// Mitsubishi GX Works2 project: 55.编码器多点定位控制   PLC: FX3U/FX3UC

PROGRAM MAIN
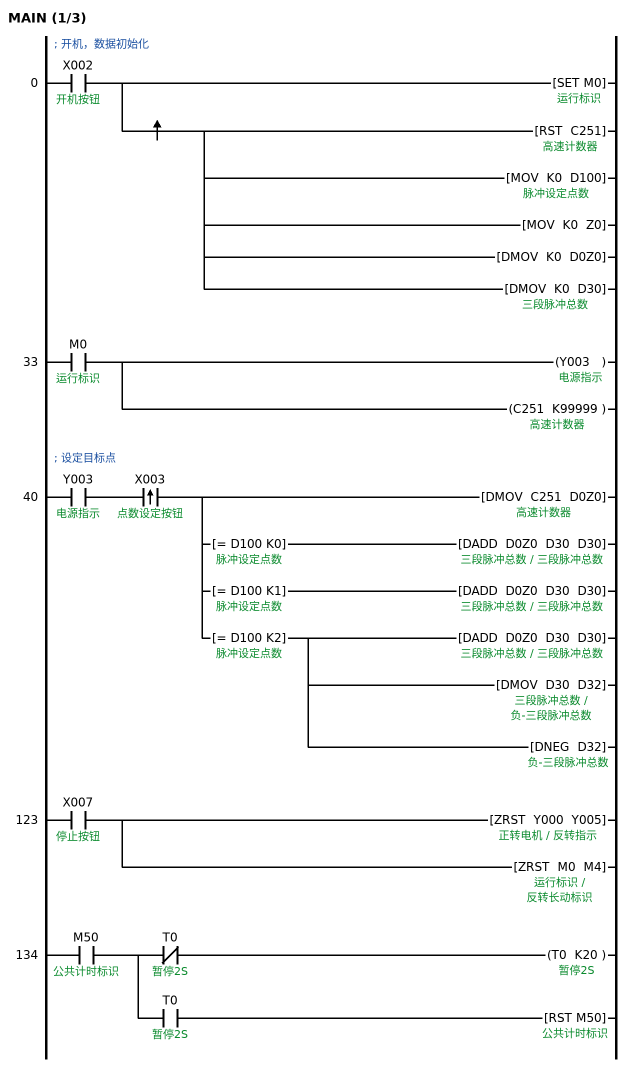
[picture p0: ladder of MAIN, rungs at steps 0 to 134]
; 开机，数据初始化
0     LD      X002  ; 开机按钮
      SET     M0  ; 运行标识
      MEP
      RST     C251  ; 高速计数器
      MOV     K0 D100  ; 脉冲设定点数
      MOV     K0 Z0
      DMOV    K0 D0Z0
      DMOV    K0 D30  ; 三段脉冲总数
33    LD      M0  ; 运行标识
      OUT     Y003  ; 电源指示
      OUT     C251 K99999  ; 高速计数器
; 设定目标点
40    LD      Y003  ; 电源指示
      ANDP    X003  ; 点数设定按钮
      DMOV    C251 D0Z0
      MPS
      AND=    D100 K0  ; 脉冲设定点数
      DADD    D0Z0 D30 D30
      MRD
      AND=    D100 K1  ; 脉冲设定点数
      DADD    D0Z0 D30 D30
      MPP
      AND=    D100 K2  ; 脉冲设定点数
      DADD    D0Z0 D30 D30
      DMOV    D30 D32  ; 负-三段脉冲总数
      DNEG    D32
        [note] 取反：得出反转电机的脉冲数
123   LD      X007  ; 停止按钮
      ZRST    Y000 Y005  ; 正转电机 / 反转指示
      ZRST    M0 M4  ; 反转长动标识
134   LD      M50  ; 公共计时标识
      MPS
      ANI     T0  ; 暂停2S
      OUT     T0 K20  ; 暂停2S
      MPP
      AND     T0  ; 暂停2S
      RST     M50  ; 公共计时标识
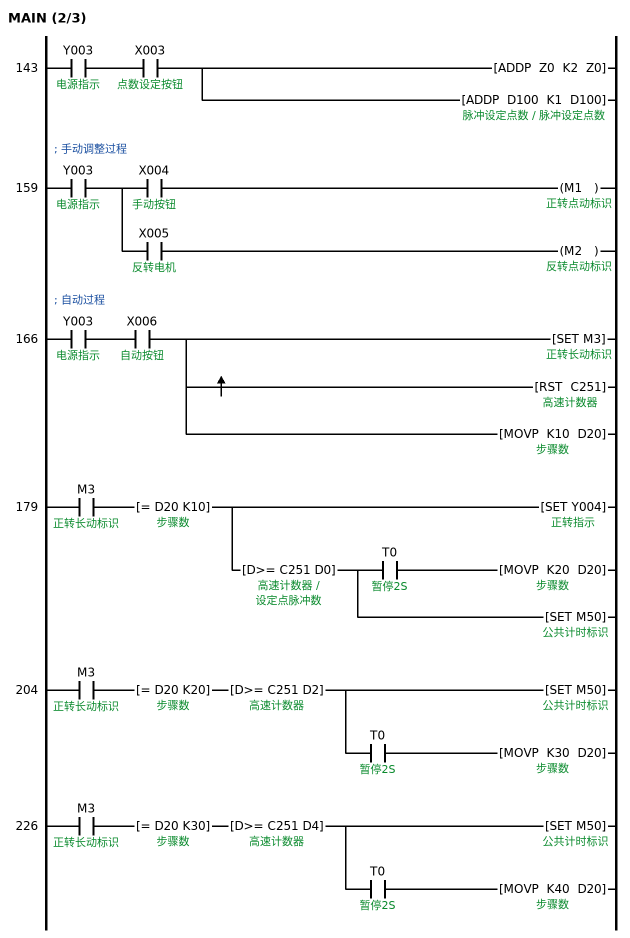
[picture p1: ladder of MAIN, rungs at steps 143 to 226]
143   LD      Y003  ; 电源指示
      AND     X003  ; 点数设定按钮
      ADDP    Z0 K2 Z0
        [note] 目标脉冲数z0自加二
      ADDP    D100 K1 D100
        [note] 目标点数D100自加一
; 手动调整过程
159   LD      Y003  ; 电源指示
      MPS
      AND     X004  ; 手动按钮
      OUT     M1  ; 正转点动标识
      MPP
      AND     X005  ; 反转电机
      OUT     M2  ; 反转点动标识
; 自动过程
166   LD      Y003  ; 电源指示
      AND     X006  ; 自动按钮
      SET     M3  ; 正转长动标识
      MPS
      MEP
      RST     C251  ; 高速计数器
      MPP
      MOVP    K10 D20  ; 步骤数
179   LD      M3  ; 正转长动标识
      AND=    D20 K10  ; 步骤数
      SET     Y004  ; 正转指示
      ANDD>=  C251 D0  ; 高速计数器 / 设定点脉冲数
      MPS
      AND     T0  ; 暂停2S
      MOVP    K20 D20
      MPP
      SET     M50  ; 公共计时标识
204   LD      M3  ; 正转长动标识
      AND=    D20 K20  ; 步骤数
      ANDD>=  C251 D2  ; 高速计数器
      SET     M50  ; 公共计时标识
      AND     T0  ; 暂停2S
      MOVP    K30 D20
226   LD      M3  ; 正转长动标识
      AND=    D20 K30  ; 步骤数
      ANDD>=  C251 D4  ; 高速计数器
      SET     M50  ; 公共计时标识
      AND     T0  ; 暂停2S
      MOVP    K40 D20
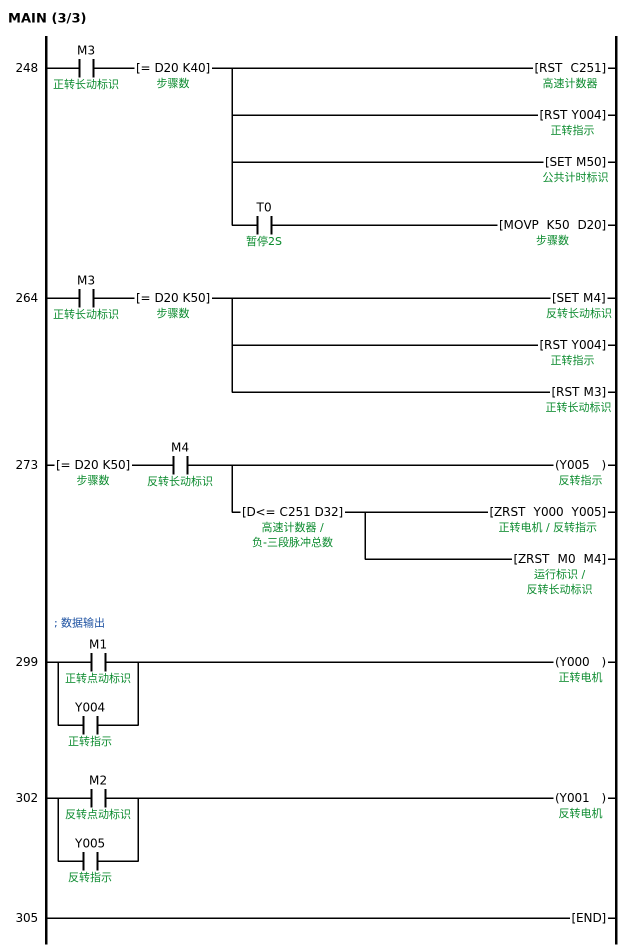
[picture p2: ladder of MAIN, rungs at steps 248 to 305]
248   LD      M3  ; 正转长动标识
      AND=    D20 K40  ; 步骤数
      RST     C251  ; 高速计数器
      RST     Y004  ; 正转指示
      SET     M50  ; 公共计时标识
      AND     T0  ; 暂停2S
      MOVP    K50 D20
264   LD      M3  ; 正转长动标识
      AND=    D20 K50  ; 步骤数
      SET     M4  ; 反转长动标识
      RST     Y004  ; 正转指示
      RST     M3  ; 正转长动标识
273   LD=     D20 K50  ; 步骤数
      AND     M4  ; 反转长动标识
      OUT     Y005  ; 反转指示
      ANDD<=  C251 D32  ; 高速计数器 / 负-三段脉冲总数
      ZRST    Y000 Y005
      ZRST    M0 M4
; 数据输出
299   LD      M1  ; 正转点动标识
      OR      Y004  ; 正转指示
      OUT     Y000  ; 正转电机
302   LD      M2  ; 反转点动标识
      OR      Y005  ; 反转指示
      OUT     Y001  ; 反转电机
305   END
END_PROGRAM

// device comments not shown above
C253  ; 手动脉冲数
C254  ; 手动脉冲数
D31  ; 三点脉冲总数
